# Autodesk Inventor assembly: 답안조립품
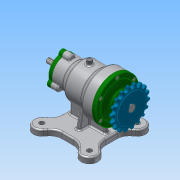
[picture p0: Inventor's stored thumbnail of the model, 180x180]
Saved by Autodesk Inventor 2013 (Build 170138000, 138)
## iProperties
Created: 2017-03
Part Number: 답안조립품
Document SubType Name: Assembly
Designer: Administrator
Author: Administrator
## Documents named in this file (14)
- C:\Users\Administrator\Desktop\470307V1012\답안조립품.iam
- C:\Users\Administrator\Desktop\470307V1012\본체.ipt
- C:\Users\Administrator\Desktop\470307V1012\뒤커버.ipt
- C:\Users\Administrator\Desktop\470307V1012\오일 실 10 20 7.ipt
- C:\Users\Administrator\Desktop\470307V1012\베어링-6200.ipt
- C:\Users\Administrator\Desktop\470307V1012\축.ipt
- C:\Users\Administrator\Desktop\470307V1012\베어링-6203.ipt
- C:\Users\Administrator\Desktop\470307V1012\앞커버.ipt
- C:\Users\Administrator\Desktop\470307V1012\오일 실 17 30 8.ipt
- C:\Users\Administrator\Desktop\470307V1012\키5x5.ipt
- C:\Users\Administrator\Desktop\470307V1012\스프로킷.ipt
- C:\Users\Administrator\Desktop\470307V1012\볼트 M5 x 10.ipt
- 볼트 M5 x 10.ipt
- C:\Users\Administrator\Desktop\470307V1012\볼트 M4 x 12.ipt
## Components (9 placed, 1 different names)
1. ISO 4762 M4 x 12:1
2. ISO 4762 M4 x 12:2
3. ISO 4762 M4 x 12:3
4. ISO 4762 M4 x 12:4
5. ISO 4762 M4 x 12:5
6. ISO 4762 M4 x 12:6
7. ISO 4762 M4 x 12:7
8. ISO 4762 M4 x 12:8
9. ISO 4762 M4 x 12:9
